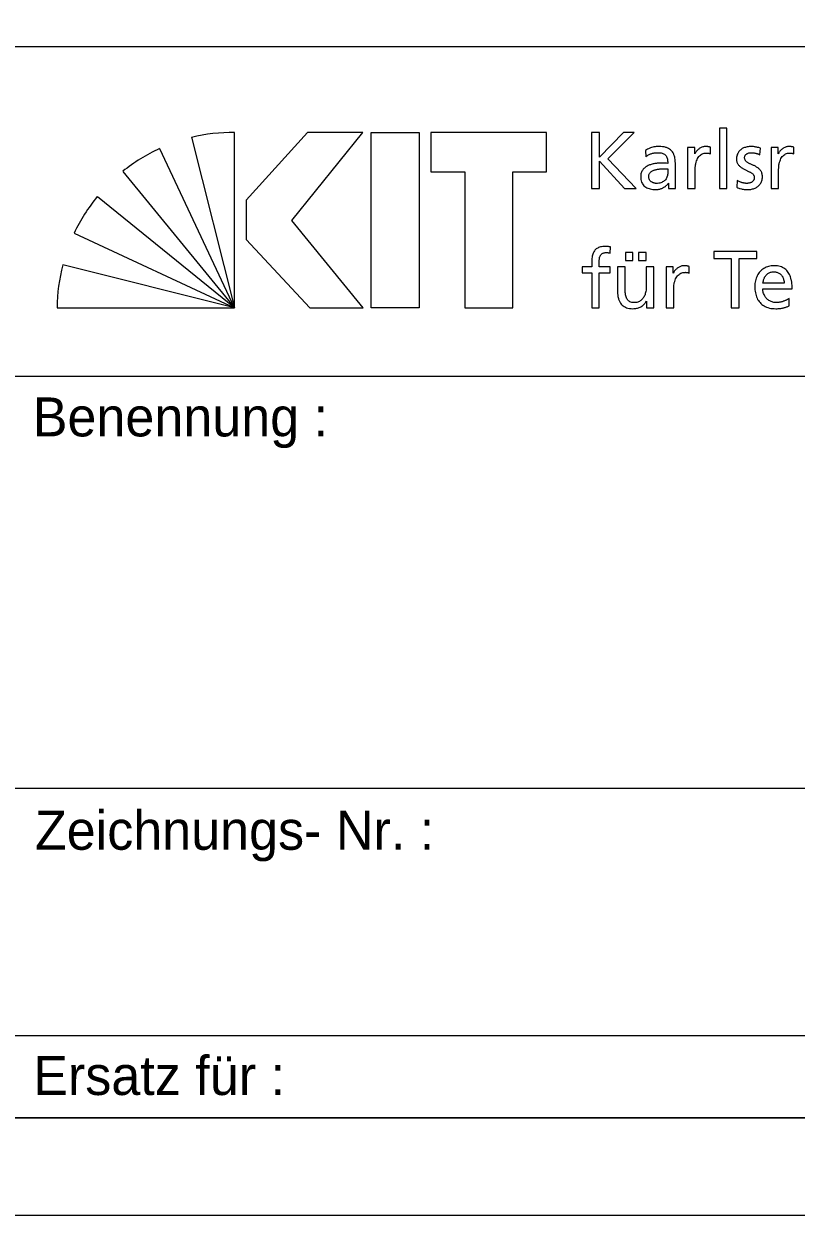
# Model space of a CAD drawing. Extents: x 0 to 23.8, y 0 to 16.8.
# Drawn here: x 22.013 to 22.807, y 0 to 1.223 of the extents above; entities that cross this region are included whole.
import ezdxf

# ---------------------------------------------------------------- set-up
doc = ezdxf.new("R2010")
doc.units = 0
doc.layers.add('90_Plankopf', color=7, linetype='Continuous')

msp = doc.modelspace()

# ---------------------------------------------------------------- linework, layer by layer
at = {"layer": '90_Plankopf'}
for p, q in [((20.1224, 1.1998), (23.68, 1.1998)), ((20.1224, 1.1998), (23.68, 1.1998)), ((22.1855, 1.1067), (22.2296, 0.9317)), ((22.2296, 0.9317), (22.2296, 1.1117)), ((22.5962, 1.1117), (22.5962, 1.0541)), ((22.2296, 0.9317), (22.1527, 1.095)), ((22.6516, 1.0932), (22.652, 1.0866)), ((22.7185, 1.0897), (22.7185, 1.0966)), ((22.7691, 1.0888), (22.7698, 1.0956)), ((22.8042, 1.0897), (22.8042, 1.0966)), ((22.6824, 1.0624), (22.6824, 1.0798)), ((22.1149, 1.0717), (22.2296, 0.9317)), ((22.6746, 1.0742), (22.6746, 1.0705)), ((22.5962, 1.0541), (22.6044, 1.0541)), ((22.6301, 1.0541), (22.6422, 1.0541)), ((22.7459, 1.0624), (22.7455, 1.0554)), ((22.2296, 0.9317), (22.0887, 1.0457)), ((22.0648, 1.0083), (22.2296, 0.9317)), ((22.6155, 0.9879), (22.6158, 0.9941)), ((22.2296, 0.9317), (22.0532, 0.9758)), ((22.6965, 0.9673), (22.6965, 0.9742)), ((22.7941, 0.9568), (22.7723, 0.9568)), ((22.7723, 0.951), (22.8024, 0.951)), ((22.0473, 0.9317), (22.2296, 0.9317)), ((22.7992, 0.9335), (22.7992, 0.9412)), ((22, 0.8614), (23.68, 0.8614)), ((22, 0.4384), (23.68, 0.4384)), ((22, 0.1846), (23.68, 0.1846)), ((23.68, 0.1), (20.1224, 0.1)), ((20.356, 0.1), (23.68, 0.1)), ((20.356, 0.1), (23.68, 0.1))]:
    msp.add_line(p, q, dxfattribs=at)
for points in [[(0, 0), (23.78, 0), (23.78, 16.82), (0, 16.82)], [(0.5, 0.1), (23.68, 0.1), (23.68, 16.72), (0.5, 16.72)], [(22.3613, 1.1117), (22.3047, 1.1117), (22.2415, 1.042), (22.2415, 1.0018), (22.3068, 0.9317), (22.3617, 0.9317), (22.2884, 1.0213)], [(22.4194, 1.1117), (22.4194, 0.9317), (22.37, 0.9317), (22.37, 1.1117)], [(22.4312, 1.1117), (22.4312, 1.0712), (22.466, 1.0712), (22.466, 0.9317), (22.5154, 0.9317), (22.5154, 1.0712), (22.5502, 1.0712), (22.5502, 1.1117)]]:
    msp.add_lwpolyline(points, close=True, dxfattribs=at)
for points in [[(22.7276, 1.0541), (22.7354, 1.0541), (22.7354, 1.116), (22.7276, 1.116), (22.7276, 1.0541)], [(22.6422, 1.0541), (22.6129, 1.0845), (22.64, 1.1117), (22.629, 1.1117), (22.6044, 1.0864), (22.6044, 1.1117), (22.5962, 1.1117)], [(22.7024, 1.0897), (22.7023, 1.0897), (22.7023, 1.0962), (22.695, 1.0962), (22.695, 1.0541), (22.7028, 1.0541), (22.7028, 1.0733)], [(22.7881, 1.0897), (22.788, 1.0897), (22.788, 1.0962), (22.7807, 1.0962), (22.7807, 1.0541), (22.7885, 1.0541), (22.7885, 1.0733)], [(22.6044, 1.0541), (22.6044, 1.0823), (22.6301, 1.0541)], [(22.6753, 1.0596), (22.6754, 1.0596), (22.6754, 1.0541), (22.6827, 1.0541)], [(22.6311, 0.9885), (22.6311, 0.9803), (22.6388, 0.9803), (22.6388, 0.9885), (22.6311, 0.9885)], [(22.6446, 0.9885), (22.6446, 0.9803), (22.6524, 0.9803), (22.6524, 0.9885), (22.6446, 0.9885)], [(22.7398, 0.9317), (22.7481, 0.9317), (22.7481, 0.9821), (22.766, 0.9821), (22.766, 0.9893), (22.7219, 0.9893), (22.7219, 0.9821), (22.7398, 0.9821), (22.7398, 0.9317)], [(22.5965, 0.9777), (22.5965, 0.9738), (22.5866, 0.9738), (22.5866, 0.9676), (22.5965, 0.9676), (22.5965, 0.9317), (22.6042, 0.9317), (22.6042, 0.9676), (22.6154, 0.9676), (22.6154, 0.9738), (22.6042, 0.9738), (22.6042, 0.9784)], [(22.6308, 0.952), (22.6308, 0.9738), (22.6231, 0.9738), (22.6231, 0.9488)], [(22.6603, 0.9317), (22.6603, 0.9738), (22.6525, 0.9738), (22.6525, 0.9543)], [(22.6804, 0.9673), (22.6803, 0.9673), (22.6803, 0.9738), (22.673, 0.9738), (22.673, 0.9317), (22.6808, 0.9317), (22.6808, 0.9509)], [(22.6526, 0.9384), (22.6528, 0.9384), (22.6528, 0.9317), (22.6603, 0.9317)]]:
    msp.add_lwpolyline(points, dxfattribs=at)
for centre, start, end in [((22.229, 0.9211), 89.8053, 103.1895), ((22.2332, 0.9224), 115.0126, 128.3968), ((22.2363, 0.9253), 140.7898, 154.174), ((22.2378, 0.9288), 165.7222, 179.1064)]:
    msp.add_arc(centre, 0.1906, start, end, dxfattribs=at)
for points in [[(22.6824, 1.0798), (22.6824, 1.0836), (22.6818, 1.0868), (22.6807, 1.0894), (22.6795, 1.092), (22.6777, 1.0939), (22.6752, 1.0952), (22.6727, 1.0965), (22.6694, 1.0972), (22.6654, 1.0972), (22.6628, 1.0972), (22.6603, 1.0968), (22.658, 1.0961), (22.6556, 1.0954), (22.6535, 1.0944), (22.6516, 1.0932)], [(22.652, 1.0866), (22.6531, 1.0875), (22.6543, 1.0883), (22.6556, 1.0889), (22.6569, 1.0896), (22.6583, 1.0901), (22.6598, 1.0904), (22.6613, 1.0908), (22.6627, 1.0909), (22.6642, 1.0909), (22.6668, 1.0909), (22.6688, 1.0905), (22.6704, 1.0897), (22.6719, 1.0889), (22.673, 1.0877), (22.6736, 1.086), (22.6743, 1.0844), (22.6746, 1.0824), (22.6746, 1.0799)], [(22.7185, 1.0966), (22.718, 1.0967), (22.7175, 1.0968), (22.717, 1.0969), (22.7165, 1.097), (22.716, 1.0971), (22.7154, 1.0971), (22.7148, 1.0972), (22.7142, 1.0972), (22.7134, 1.0972), (22.7119, 1.0972), (22.7105, 1.0969), (22.709, 1.0962), (22.7076, 1.0956), (22.7064, 1.0947), (22.7052, 1.0936), (22.7041, 1.0925), (22.7031, 1.0912), (22.7024, 1.0897)], [(22.7028, 1.0733), (22.7028, 1.0768), (22.7033, 1.0799), (22.7042, 1.0824), (22.7051, 1.085), (22.7065, 1.087), (22.7082, 1.0883), (22.7099, 1.0897), (22.7119, 1.0904), (22.7142, 1.0904), (22.7149, 1.0904), (22.7156, 1.0904), (22.7164, 1.0903), (22.7171, 1.0902), (22.7178, 1.09), (22.7185, 1.0897)], [(22.7698, 1.0956), (22.7683, 1.096), (22.7667, 1.0964), (22.7652, 1.0967), (22.7636, 1.097), (22.7619, 1.0972), (22.7601, 1.0972), (22.7581, 1.0972), (22.7561, 1.0969), (22.7543, 1.0964), (22.7525, 1.0959), (22.7509, 1.0951), (22.7496, 1.094), (22.7482, 1.0929), (22.7472, 1.0916), (22.7464, 1.09), (22.7457, 1.0883), (22.7453, 1.0864), (22.7453, 1.0842), (22.7453, 1.0826), (22.7456, 1.0811), (22.7463, 1.0799), (22.7469, 1.0787), (22.7478, 1.0776), (22.7489, 1.0767), (22.75, 1.0758), (22.7512, 1.075), (22.7525, 1.0743), (22.7538, 1.0736), (22.7551, 1.0729), (22.7563, 1.0723), (22.7576, 1.0717), (22.7588, 1.0711), (22.7599, 1.0704), (22.761, 1.0698), (22.7619, 1.0691), (22.7625, 1.0683), (22.7632, 1.0675), (22.7635, 1.0665), (22.7635, 1.0654), (22.7635, 1.0643), (22.7633, 1.0633), (22.7628, 1.0626), (22.7623, 1.0618), (22.7617, 1.0612), (22.7609, 1.0607), (22.7601, 1.0602), (22.7593, 1.0599), (22.7583, 1.0597), (22.7574, 1.0595), (22.7565, 1.0594), (22.7556, 1.0594), (22.7548, 1.0594), (22.7539, 1.0595), (22.7528, 1.0597), (22.7517, 1.0599), (22.7505, 1.0603), (22.7493, 1.0607), (22.7481, 1.0612), (22.747, 1.0617), (22.7459, 1.0624)], [(22.7455, 1.0554), (22.7473, 1.0545), (22.7492, 1.0539), (22.7512, 1.0536), (22.7531, 1.0532), (22.7551, 1.0531), (22.7571, 1.0531), (22.759, 1.0531), (22.7608, 1.0534), (22.7625, 1.0539), (22.7643, 1.0544), (22.7659, 1.0552), (22.7673, 1.0563), (22.7686, 1.0574), (22.7697, 1.0588), (22.7705, 1.0604), (22.7714, 1.0621), (22.7718, 1.064), (22.7718, 1.0662), (22.7718, 1.0682), (22.7714, 1.0698), (22.7708, 1.0711), (22.7701, 1.0724), (22.7692, 1.0736), (22.7682, 1.0745), (22.7671, 1.0754), (22.7659, 1.0762), (22.7646, 1.0769), (22.7633, 1.0776), (22.762, 1.0782), (22.7607, 1.0787), (22.7594, 1.0793), (22.7582, 1.0799), (22.7572, 1.0805), (22.7561, 1.0812), (22.7552, 1.0819), (22.7545, 1.0827), (22.7539, 1.0836), (22.7536, 1.0846), (22.7535, 1.0858), (22.7536, 1.087), (22.7539, 1.0879), (22.7546, 1.0887), (22.7553, 1.0894), (22.7562, 1.09), (22.7573, 1.0904), (22.7584, 1.0908), (22.7596, 1.0909), (22.761, 1.0909), (22.7614, 1.0909), (22.762, 1.0909), (22.7628, 1.0908), (22.7635, 1.0906), (22.7643, 1.0905), (22.7651, 1.0903), (22.7659, 1.0901), (22.7667, 1.0898), (22.7674, 1.0896), (22.7681, 1.0893), (22.7687, 1.0891), (22.7691, 1.0888)], [(22.8042, 1.0966), (22.8037, 1.0967), (22.8032, 1.0968), (22.8027, 1.0969), (22.8022, 1.097), (22.8017, 1.0971), (22.8011, 1.0971), (22.8005, 1.0972), (22.7999, 1.0972), (22.7991, 1.0972), (22.7976, 1.0972), (22.7962, 1.0969), (22.7947, 1.0962), (22.7933, 1.0956), (22.7921, 1.0947), (22.7909, 1.0936), (22.7898, 1.0925), (22.7888, 1.0912), (22.7881, 1.0897)], [(22.7885, 1.0733), (22.7885, 1.0768), (22.789, 1.0799), (22.7899, 1.0824), (22.7908, 1.085), (22.7922, 1.087), (22.7939, 1.0883), (22.7956, 1.0897), (22.7976, 1.0904), (22.7999, 1.0904), (22.8006, 1.0904), (22.8013, 1.0904), (22.8021, 1.0903), (22.8028, 1.0902), (22.8035, 1.09), (22.8042, 1.0897)], [(22.6746, 1.0799), (22.6736, 1.08), (22.6727, 1.08), (22.6718, 1.0801), (22.6709, 1.0801), (22.67, 1.0801), (22.6692, 1.0801), (22.6683, 1.0801), (22.6674, 1.0801), (22.6664, 1.0801), (22.6647, 1.0801), (22.663, 1.08), (22.6613, 1.0797), (22.6595, 1.0794), (22.6577, 1.0789), (22.656, 1.0783), (22.6543, 1.0776), (22.6528, 1.0768), (22.6514, 1.0757), (22.65, 1.0746), (22.6489, 1.0733), (22.6481, 1.0718), (22.6472, 1.0702), (22.6468, 1.0684), (22.6468, 1.0662), (22.6468, 1.0632), (22.6475, 1.0607), (22.6488, 1.0588), (22.6501, 1.0568), (22.6519, 1.0554), (22.6542, 1.0545), (22.6565, 1.0536), (22.6592, 1.0531), (22.6622, 1.0531), (22.664, 1.0531), (22.6656, 1.0534), (22.667, 1.0538), (22.6684, 1.0542), (22.6697, 1.0547), (22.6707, 1.0554), (22.6718, 1.056), (22.6727, 1.0567), (22.6735, 1.0575), (22.6742, 1.0582), (22.6748, 1.0589), (22.6753, 1.0596)], [(22.6746, 1.0705), (22.6746, 1.0684), (22.6742, 1.0665), (22.6733, 1.0648), (22.6724, 1.0631), (22.6711, 1.0618), (22.6693, 1.0609), (22.6676, 1.0599), (22.6654, 1.0594), (22.6629, 1.0594), (22.662, 1.0594), (22.6611, 1.0596), (22.6602, 1.0598), (22.6593, 1.0601), (22.6584, 1.0606), (22.6576, 1.0611), (22.6569, 1.0617), (22.6562, 1.0625), (22.6558, 1.0633), (22.6553, 1.0641), (22.6551, 1.0651), (22.655, 1.0662), (22.6551, 1.0677), (22.6554, 1.069), (22.6562, 1.0699), (22.6569, 1.0709), (22.6578, 1.0717), (22.659, 1.0723), (22.6601, 1.0729), (22.6614, 1.0733), (22.6627, 1.0736), (22.664, 1.0739), (22.6653, 1.0741), (22.6665, 1.0742), (22.6677, 1.0743), (22.6688, 1.0743), (22.6697, 1.0743), (22.6705, 1.0743), (22.6713, 1.0743), (22.6721, 1.0743), (22.673, 1.0742), (22.6738, 1.0742), (22.6746, 1.0742)], [(22.6827, 1.0541), (22.6826, 1.0545), (22.6826, 1.0551), (22.6825, 1.0557), (22.6825, 1.0564), (22.6824, 1.0573), (22.6824, 1.0584), (22.6824, 1.0595), (22.6824, 1.0608), (22.6824, 1.0624)], [(22.6158, 0.9941), (22.615, 0.9942), (22.6142, 0.9944), (22.6134, 0.9945), (22.6125, 0.9946), (22.6116, 0.9946), (22.6106, 0.9946), (22.6078, 0.9946), (22.6054, 0.9942), (22.6036, 0.9934), (22.6017, 0.9926), (22.6003, 0.9915), (22.5992, 0.99), (22.5982, 0.9885), (22.5975, 0.9867), (22.5971, 0.9847), (22.5967, 0.9826), (22.5965, 0.9803), (22.5965, 0.9777)], [(22.6042, 0.9784), (22.6042, 0.9798), (22.6043, 0.9811), (22.6045, 0.9823), (22.6046, 0.9835), (22.605, 0.9846), (22.6055, 0.9855), (22.606, 0.9864), (22.6068, 0.9871), (22.6078, 0.9876), (22.6088, 0.9881), (22.6101, 0.9883), (22.6118, 0.9883), (22.6124, 0.9883), (22.6131, 0.9883), (22.6138, 0.9882), (22.6144, 0.9881), (22.615, 0.988), (22.6155, 0.9879)], [(22.6965, 0.9742), (22.696, 0.9743), (22.6955, 0.9744), (22.695, 0.9745), (22.6945, 0.9746), (22.694, 0.9747), (22.6934, 0.9747), (22.6928, 0.9748), (22.6922, 0.9748), (22.6914, 0.9748), (22.6899, 0.9748), (22.6885, 0.9745), (22.687, 0.9738), (22.6856, 0.9732), (22.6844, 0.9723), (22.6832, 0.9712), (22.6821, 0.9701), (22.6811, 0.9688), (22.6804, 0.9673)], [(22.6808, 0.9509), (22.6808, 0.9544), (22.6813, 0.9575), (22.6822, 0.96), (22.6832, 0.9626), (22.6845, 0.9646), (22.6862, 0.9659), (22.6879, 0.9673), (22.6899, 0.968), (22.6922, 0.968), (22.6929, 0.9681), (22.6936, 0.968), (22.6944, 0.9679), (22.6951, 0.9678), (22.6958, 0.9676), (22.6965, 0.9673)], [(22.8024, 0.951), (22.8024, 0.9544), (22.8021, 0.9576), (22.8014, 0.9605), (22.8008, 0.9634), (22.7998, 0.9659), (22.7984, 0.968), (22.7969, 0.9701), (22.795, 0.9718), (22.7926, 0.973), (22.7902, 0.9742), (22.7873, 0.9748), (22.7838, 0.9748), (22.7808, 0.9748), (22.7781, 0.9743), (22.7757, 0.9732), (22.7733, 0.9722), (22.7712, 0.9707), (22.7695, 0.9688), (22.7677, 0.9669), (22.7664, 0.9647), (22.7655, 0.9621), (22.7646, 0.9595), (22.7641, 0.9567), (22.7641, 0.9535), (22.7641, 0.9501), (22.7645, 0.947), (22.7654, 0.9442), (22.7662, 0.9414), (22.7676, 0.939), (22.7694, 0.937), (22.7712, 0.935), (22.7734, 0.9334), (22.7762, 0.9324), (22.7789, 0.9313), (22.7821, 0.9308), (22.7859, 0.9307), (22.7882, 0.9308), (22.7901, 0.9309), (22.7917, 0.9312), (22.7933, 0.9315), (22.7947, 0.9319), (22.7959, 0.9323), (22.7971, 0.9327), (22.7982, 0.9331), (22.7992, 0.9335)], [(22.7723, 0.9568), (22.7725, 0.9582), (22.7728, 0.9596), (22.7733, 0.9609), (22.7738, 0.9623), (22.7744, 0.9636), (22.7754, 0.9647), (22.7762, 0.9659), (22.7774, 0.9668), (22.7787, 0.9675), (22.7801, 0.9682), (22.7817, 0.9685), (22.7836, 0.9685), (22.7853, 0.9685), (22.7868, 0.9682), (22.7881, 0.9676), (22.7894, 0.967), (22.7905, 0.9662), (22.7914, 0.9651), (22.7923, 0.964), (22.793, 0.9628), (22.7934, 0.9614), (22.7939, 0.96), (22.7941, 0.9584), (22.7941, 0.9568)], [(22.6525, 0.9543), (22.6525, 0.9518), (22.6523, 0.9494), (22.6518, 0.9473), (22.6513, 0.9452), (22.6505, 0.9434), (22.6495, 0.9418), (22.6484, 0.9403), (22.6471, 0.9391), (22.6455, 0.9383), (22.6439, 0.9374), (22.6419, 0.937), (22.6397, 0.937), (22.6375, 0.9371), (22.6357, 0.9378), (22.6344, 0.9389), (22.6331, 0.94), (22.6322, 0.9417), (22.6316, 0.9439), (22.6311, 0.946), (22.6308, 0.9488), (22.6308, 0.952)], [(22.6231, 0.9488), (22.6231, 0.945), (22.6236, 0.9418), (22.6247, 0.9391), (22.6259, 0.9364), (22.6276, 0.9343), (22.6299, 0.9329), (22.6322, 0.9315), (22.6352, 0.9308), (22.6388, 0.9307), (22.6408, 0.9308), (22.6427, 0.9311), (22.6445, 0.9317), (22.6463, 0.9323), (22.6479, 0.9332), (22.6493, 0.9343), (22.6507, 0.9354), (22.6518, 0.9368), (22.6526, 0.9384)], [(22.7992, 0.9412), (22.7987, 0.9408), (22.798, 0.9404), (22.797, 0.9399), (22.7961, 0.9394), (22.7951, 0.939), (22.7939, 0.9385), (22.7927, 0.9381), (22.7914, 0.9377), (22.7901, 0.9374), (22.7888, 0.9372), (22.7875, 0.937), (22.7862, 0.937), (22.7843, 0.937), (22.7826, 0.9374), (22.7809, 0.938), (22.7793, 0.9387), (22.7778, 0.9397), (22.7765, 0.9409), (22.7752, 0.9421), (22.7742, 0.9436), (22.7735, 0.9453), (22.7727, 0.9471), (22.7723, 0.949), (22.7723, 0.951)]]:
    msp.add_open_spline(points, degree=3, dxfattribs=at)

# ---------------------------------------------------------------- texts
for s, p in [('Benennung :', (22.0223, 0.7996)), ('Zeichnungs- Nr. :', (22.0245, 0.3752)), ('Ersatz für :', (22.0228, 0.1234))]:
    msp.add_text(s, height=0.04, dxfattribs=at).set_placement(p)

doc.saveas('drawing.dxf')
